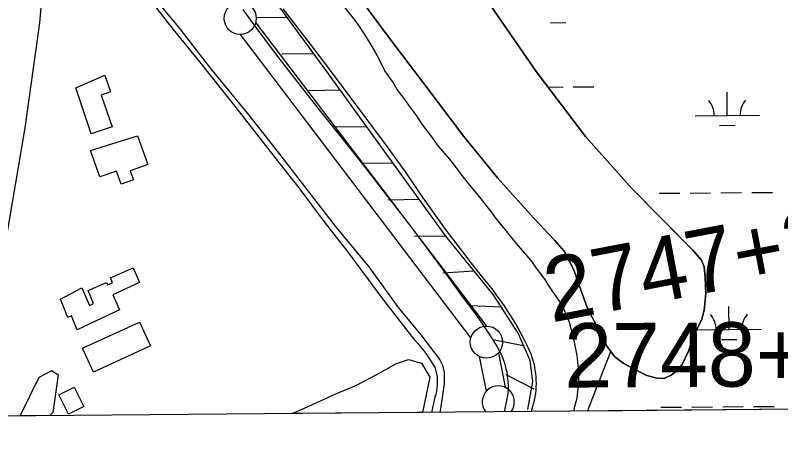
# Model space of a CAD drawing. Extents: x 3568792 to 3606828, y 529143 to 554785.
# Drawn here: x 3574735 to 3575924, y 534531 to 535185 of the extents above; entities that cross this region are included whole.
import ezdxf

# ---------------------------------------------------------------- set-up
doc = ezdxf.new("R2010")
doc.units = 0
for name, color, linetype in [('V-BLDG-OTLN', 7, 'Continuous'), ('V-FLOD-BASE', 7, 'Continuous'), ('V-GRID-FRAM', 7, 'Continuous'), ('V-LEVE-TOET', 7, 'Continuous'), ('V-ROAD-CNTR', 7, 'Continuous'), ('V-RRAP-FSHR', 7, 'Continuous'), ('V-SITE-VEGE', 7, 'Continuous'), ('V-SURV-IDEN', 7, 'Continuous'), ('V-SURV-LINE', 7, 'Continuous'), ('V-TOPO-SHOR', 7, 'Continuous'), ('V-WETL-SWMP', 7, 'Continuous')]:
    doc.layers.add(name, color=color, linetype=linetype)

msp = doc.modelspace()

# ---------------------------------------------------------------- linework, layer by layer
at = {"layer": 'V-BLDG-OTLN'}
for points in [[(3574828.5, 535072.1), (3574873.6, 535091.6), (3574882.4, 535065.6), (3574868.1, 535060.8), (3574884.8, 535011.3), (3574852.6, 535000.5)], [(3574924.4, 534997.2), (3574940.4, 534952.7), (3574913.1, 534942.8), (3574918, 534929.2), (3574899, 534922.4), (3574891.7, 534942.7), (3574866.1, 534933.5), (3574851.3, 534974.6)], [(3574804.8, 534743.6), (3574837.7, 534761.3), (3574849.9, 534733.7), (3574856.1, 534736.9), (3574847.6, 534756.8), (3574876.3, 534769.5), (3574878, 534765.6), (3574885.7, 534769), (3574882.5, 534776.8), (3574917.6, 534792.5), (3574927.4, 534769.4), (3574886.2, 534750.5), (3574896.5, 534726.8), (3574830.9, 534695.7), (3574821.9, 534717.4), (3574816.1, 534715.1)], [(3574838.7, 534667.3), (3574927.3, 534707.8), (3574944.4, 534670.9), (3574856, 534630)], [(3574825.8, 534607), (3574841.1, 534576.9), (3574817.3, 534564.8), (3574802.1, 534595)]]:
    msp.add_lwpolyline(points, close=True, dxfattribs=at)
at = {"layer": 'V-FLOD-BASE'}
msp.add_lwpolyline([(3575088.3, 535193.6), (3575102.7, 535173.5), (3575122.3, 535147.1), (3575142.1, 535120.8), (3575162.2, 535094.8), (3575182.4, 535068.8), (3575202.8, 535043.1), (3575223.4, 535017.4), (3575248.8, 534985.6), (3575274.1, 534953.6), (3575299.1, 534921.5), (3575324, 534889.2), (3575348.7, 534856.8), (3575373.1, 534824.2), (3575390.6, 534800.7), (3575407.9, 534777), (3575425.1, 534753.2), (3575433.9, 534741.6), (3575442.6, 534729.9), (3575451.2, 534718), (3575459.5, 534706), (3575467.7, 534693.9), (3575475.7, 534681.7), (3575483.4, 534669.4), (3575486, 534664.8), (3575488.4, 534660.1), (3575490.5, 534655.4), (3575492.5, 534650.5), (3575494.2, 534645.6), (3575495.8, 534640.6), (3575497.1, 534635.5), (3575498.2, 534630.4), (3575499.1, 534625.2), (3575499.7, 534620), (3575500.1, 534614.8), (3575500.3, 534609.6), (3575500.3, 534604.3), (3575500, 534599.1), (3575499.6, 534593.9), (3575494.3, 534568.5)], dxfattribs=at)
at = {"layer": 'V-GRID-FRAM'}
msp.add_lwpolyline([(3570936, 552713.8), (3602582.8, 552980.8), (3602744.1, 534798.4), (3571081.5, 534531.3), (3570936, 552713.8)], dxfattribs=at)
at = {"layer": 'V-LEVE-TOET'}
for points in [[(3574956.4, 535204.1), (3574987.9, 535166.5), (3575038, 535102), (3575097.3, 535029.7), (3575143.5, 534970.8), (3575196.5, 534902.8), (3575231.6, 534856.8), (3575284, 534793.7), (3575329.8, 534730.7), (3575364.6, 534688.1), (3575394.2, 534649.5), (3575398.6, 534641), (3575401, 534629.5), (3575401.3, 534611.9), (3575395.1, 534573.2), (3575394.1, 534567.7)], [(3575150.3, 535194.9), (3575164.6, 535176.4), (3575194.3, 535137.9), (3575223.7, 535099.2), (3575252.9, 535060.4), (3575282, 535021.5), (3575310.8, 534982.3), (3575339.4, 534943.1), (3575351.7, 534924.7), (3575364.3, 534906.5), (3575376.9, 534888.4), (3575389.8, 534870.4), (3575402.8, 534852.6), (3575416, 534834.8), (3575429.3, 534817.2), (3575442.8, 534799.7), (3575456.5, 534782.4), (3575470.3, 534765.1), (3575476.5, 534757.3), (3575482.6, 534749.3), (3575488.5, 534741.2), (3575494.2, 534733), (3575499.7, 534724.6), (3575505.1, 534716.2), (3575510.3, 534707.6), (3575515.3, 534698.9), (3575520.2, 534690.2), (3575524.8, 534681.3), (3575529.3, 534672.3), (3575533.6, 534663.3), (3575535.5, 534658.4), (3575537.3, 534653.5), (3575538.8, 534648.6), (3575540.2, 534643.5), (3575541.3, 534638.4), (3575542.2, 534633.3)], [(3575542.2, 534633.3), (3575542.9, 534628.2), (3575543.4, 534623), (3575543.7, 534617.8), (3575543.8, 534612.6), (3575543.7, 534607.4), (3575543.3, 534602.2), (3575542.8, 534597), (3575542, 534591.8), (3575541, 534586.7), (3575539.8, 534581.7), (3575538.5, 534576.6), (3575536.5, 534568.9)]]:
    msp.add_lwpolyline(points, dxfattribs=at)
at = {"layer": 'V-ROAD-CNTR'}
msp.add_lwpolyline([(3574679.5, 534564.9), (3574682.8, 534585.3), (3574715.6, 534808.4), (3574750, 535010.1), (3574772.8, 535172.9), (3574780.1, 535257.5), (3574780.7, 535303.2), (3574778.8, 535343.1), (3574770, 535401.7), (3574752.2, 535470.8), (3574725.1, 535558.5), (3574678.7, 535714.1), (3574618.7, 535912.6), (3574554, 536132.9), (3574534.5, 536220.7), (3574522.9, 536264.9), (3574502.7, 536365.9), (3574469.6, 536535.8)], dxfattribs=at)
at = {"layer": 'V-RRAP-FSHR'}
for p, q in [((3575157, 535181.6), (3575108.2, 535180.8)), ((3575198.2, 535125), (3575149.4, 535124.2)), ((3575239.3, 535068.4), (3575190.5, 535067.6)), ((3575280.4, 535011.7), (3575231.6, 535010.9)), ((3575321.5, 534955), (3575272.7, 534954.2)), ((3575362.6, 534898.3), (3575313.7, 534897.6)), ((3575403.6, 534841.7), (3575354.8, 534840.9)), ((3575447.6, 534787.2), (3575398.8, 534783.8)), ((3575489.6, 534731.3), (3575440.8, 534733.1)), ((3575524.6, 534670.9), (3575476.7, 534680.4)), ((3575540.7, 534603.4), (3575497.3, 534625.7))]:
    msp.add_line(p, q, dxfattribs=at)
msp.add_lwpolyline([(3575531.2, 534572.1), (3575539, 534615.7), (3575534.6, 534648.2), (3575515.9, 534690.6), (3575477.1, 534750.6), (3575403.9, 534841.3), (3575218.5, 535097.2), (3575070.7, 535300.3), (3575019.9, 535377.2), (3574957.7, 535513.9), (3574913.3, 535625.4), (3574863.8, 535751.1), (3574795.8, 535973.3), (3574724.4, 536223.4), (3574678.3, 536411.2)], dxfattribs=at)
at = {"layer": 'V-SITE-VEGE'}
for p, q in [((3575251.7, 535236.1), (3575312.4, 535154)), ((3575265.1, 535173.6), (3575234.2, 535213.7)), ((3575543.9, 535097.7), (3575473.8, 535199.4)), ((3575275.9, 535158.2), (3575265.1, 535173.6)), ((3575287.3, 535140), (3575275.9, 535158.2)), ((3575312.4, 535154), (3575371.1, 535076.7)), ((3575293, 535130), (3575287.3, 535140)), ((3575302.6, 535111.2), (3575293, 535130)), ((3575308.8, 535098.3), (3575302.6, 535111.2)), ((3575321.4, 535081.2), (3575308.8, 535098.3)), ((3575620.9, 534996.5), (3575543.9, 535097.7)), ((3575328.2, 535069.4), (3575321.4, 535081.2)), ((3575339.1, 535055.3), (3575328.2, 535069.4)), ((3575371.1, 535076.7), (3575431.7, 534996.4)), ((3575345.9, 535045.3), (3575339.1, 535055.3)), ((3575358.5, 535028.8), (3575345.9, 535045.3)), ((3575367.1, 535015.8), (3575358.5, 535028.8)), ((3575381.9, 534995.8), (3575367.1, 535015.8)), ((3575392.2, 534981.6), (3575381.9, 534995.8)), ((3575431.7, 534996.4), (3575484.2, 534932.1)), ((3575693.5, 534915.2), (3575620.9, 534996.5)), ((3575409.4, 534961.5), (3575392.2, 534981.6)), ((3575415.1, 534954.5), (3575409.4, 534961.5)), ((3575431.1, 534933.2), (3575415.1, 534954.5)), ((3575441.4, 534920.3), (3575431.1, 534933.2)), ((3575484.2, 534932.1), (3575539.7, 534870.1)), ((3575456.3, 534902), (3575441.4, 534920.3)), ((3575787.5, 534819.5), (3575693.5, 534915.2)), ((3575475.8, 534877.8), (3575456.3, 534902)), ((3575482.1, 534868.9), (3575475.8, 534877.8)), ((3575500.4, 534845.9), (3575482.1, 534868.9)), ((3575539.7, 534870.1), (3575572.4, 534835.2)), ((3575513.6, 534830), (3575500.4, 534845.9)), ((3575572.4, 534835.2), (3575587.3, 534818.2)), ((3575532.5, 534807.6), (3575513.6, 534830)), ((3575587.3, 534818.2), (3575595.9, 534802.5)), ((3575800.8, 534804.1), (3575787.5, 534819.5)), ((3575538.2, 534801.1), (3575532.5, 534807.6)), ((3575542.8, 534794), (3575538.2, 534801.1)), ((3575595.9, 534802.5), (3575603.1, 534787.8)), ((3575805.1, 534793.8), (3575800.8, 534804.1)), ((3575547.9, 534787.5), (3575542.8, 534794)), ((3575558.2, 534773.9), (3575547.9, 534787.5)), ((3575603.1, 534787.8), (3575608.8, 534771.1)), ((3575806.9, 534777.8), (3575805.1, 534793.8)), ((3575564.5, 534763.9), (3575558.2, 534773.9)), ((3575807.8, 534752.3), (3575806.9, 534777.8)), ((3575570.2, 534755.7), (3575564.5, 534763.9)), ((3575608.8, 534771.1), (3575615.8, 534750.9)), ((3575578.2, 534743.3), (3575570.2, 534755.7)), ((3575615.8, 534750.9), (3575623.3, 534730.7)), ((3575805.1, 534726.3), (3575807.8, 534752.3)), ((3575583.3, 534735.7), (3575578.2, 534743.3)), ((3575588.9, 534723.9), (3575583.3, 534735.7)), ((3575623.3, 534730.7), (3575654.6, 534670.1)), ((3575801.5, 534712.7), (3575805.1, 534726.3)), ((3575591.8, 534718.6), (3575588.9, 534723.9)), ((3575595.7, 534707.5), (3575591.8, 534718.6)), ((3575793.2, 534695.6), (3575801.5, 534712.7)), ((3575598.5, 534697.6), (3575595.7, 534707.5)), ((3575602.9, 534679.4), (3575598.5, 534697.6)), ((3575785.6, 534677.2), (3575793.2, 534695.6)), ((3575607.8, 534656), (3575602.9, 534679.4)), ((3575780.6, 534662.5), (3575785.6, 534677.2)), ((3575654.6, 534670.1), (3575665.7, 534654.6)), ((3575609.8, 534635.6), (3575607.8, 534656)), ((3575665.7, 534654.6), (3575679.5, 534644.1)), ((3575770.7, 534641.8), (3575780.6, 534662.5)), ((3575295.4, 534625.7), (3575327.1, 534643.7)), ((3575327.1, 534643.7), (3575345.7, 534649.6)), ((3575345.7, 534649.6), (3575366, 534644.3)), ((3575366, 534644.3), (3575378.7, 534622.5)), ((3575679.5, 534644.1), (3575693.9, 534636.3)), ((3575763.6, 534632.6), (3575770.7, 534641.8)), ((3574771.6, 534622.5), (3574791.5, 534632.7)), ((3574791.5, 534632.7), (3574801.2, 534625.8)), ((3575610.2, 534623.9), (3575609.8, 534635.6)), ((3575693.9, 534636.3), (3575715.9, 534625.1)), ((3575753.6, 534625.2), (3575763.6, 534632.6)), ((3574742.1, 534562.2), (3574771.6, 534622.5)), ((3574801.2, 534625.8), (3574798.5, 534607.3)), ((3575263.7, 534609.5), (3575295.4, 534625.7)), ((3575378.7, 534622.5), (3575367.3, 534567.5)), ((3575610, 534608.8), (3575610.2, 534623.9)), ((3575715.9, 534625.1), (3575731.4, 534621)), ((3575731.4, 534621), (3575742.9, 534620.4)), ((3575742.9, 534620.4), (3575753.6, 534625.2)), ((3574798.5, 534607.3), (3574792.9, 534567.3)), ((3575232.7, 534596.4), (3575263.7, 534609.5)), ((3575607.9, 534590.1), (3575610, 534608.8)), ((3575184.2, 534574.3), (3575232.7, 534596.4)), ((3575603.6, 534575.1), (3575607.9, 534590.1)), ((3575164.7, 534565.8), (3575184.2, 534574.3)), ((3575603, 534569.5), (3575603.6, 534575.1)), ((3575948.4, 534572.4), (3575603, 534569.5)), ((3574788.1, 534562.6), (3574742.1, 534562.2)), ((3574792.9, 534567.3), (3574788.1, 534562.6)), ((3575367.3, 534567.5), (3575164.7, 534565.8))]:
    msp.add_line(p, q, dxfattribs=at)
at = {"layer": 'V-SURV-LINE'}
for points in [[(3575108.1, 535173.2), (3575466.6, 534701.8)], [(3575442.7, 534683.6), (3575084.3, 535155.1)], [(3575466.6, 534600.6), (3575455.9, 534654.2)], [(3575485.3, 534660.1), (3575496, 534606.5)]]:
    msp.add_lwpolyline(points, dxfattribs=at)
for centre in [(3575084.1, 535180.1), (3575466.7, 534676.8)]:
    msp.add_circle(centre, 25, dxfattribs=at)
msp.add_arc((3575485.2, 534583.9), 25, 322.3071, 218.6596, dxfattribs=at)
at = {"layer": 'V-TOPO-SHOR'}
msp.add_line((3575344.6, 534693.1), (3575354.4, 534680.7), dxfattribs=at)
for points in [[(3574756.1, 535561.1), (3574778.7, 535526.8), (3574796.2, 535490.7), (3574839.6, 535405.8), (3574889, 535309.9), (3574930.7, 535235.7), (3574948, 535203.3), (3574980, 535162.7), (3575020.8, 535112.3), (3575077.1, 535041.6), (3575139.8, 534961.4), (3575175.2, 534916.4), (3575214.4, 534863.6), (3575250.4, 534818.4), (3575303.6, 534746.4), (3575341, 534697.9), (3575344.6, 534693.1)], [(3575473.8, 535199.4), (3575543.9, 535097.7), (3575620.9, 534996.5), (3575693.5, 534915.2), (3575772.9, 534834.3), (3575787.5, 534819.5), (3575800.8, 534804.1), (3575805.1, 534793.8), (3575806.9, 534777.8), (3575807.8, 534752.3), (3575805.1, 534726.3), (3575801.5, 534712.7), (3575793.2, 534695.6), (3575785.6, 534677.2), (3575780.6, 534662.5), (3575770.7, 534641.8), (3575763.6, 534632.6), (3575753.6, 534625.2), (3575742.9, 534620.4), (3575731.4, 534621), (3575715.9, 534625.1), (3575693.9, 534636.3), (3575679.5, 534644.1), (3575665.7, 534654.6), (3575654.6, 534670.1), (3575647.8, 534683.2), (3575623.3, 534730.7), (3575615.8, 534750.9), (3575608.8, 534771.1), (3575603.1, 534787.8), (3575595.9, 534802.5), (3575587.3, 534818.2), (3575572.4, 534835.2), (3575539.7, 534870.1), (3575484.2, 534932.1), (3575431.7, 534996.4), (3575371.1, 535076.7), (3575312.4, 535154), (3575251.7, 535236.1)], [(3575354.4, 534680.7), (3575359.6, 534675), (3575364.6, 534669.1), (3575369.4, 534663.1), (3575374, 534656.9), (3575378.4, 534650.6), (3575382.6, 534644.2), (3575386.6, 534637.6), (3575387.7, 534633.7), (3575388.7, 534629.7), (3575389.4, 534625.6), (3575390, 534621.5), (3575390.3, 534617.4), (3575390.3, 534613.3), (3575390.2, 534609.2), (3575389.8, 534605.1), (3575389.2, 534601), (3575388.4, 534597), (3575387.3, 534593), (3575386, 534589.1), (3575381.5, 534567.6)]]:
    msp.add_lwpolyline(points, dxfattribs=at)
at = {"layer": 'V-WETL-SWMP'}
for p, q in [((3575543.9, 535097.7), (3575473.8, 535199.4)), ((3575566.3, 535173.2), (3575590.3, 535173.4)), ((3575620.9, 534996.5), (3575543.9, 535097.7)), ((3575562.5, 535073.2), (3575585.8, 535073.4)), ((3575601.8, 535073.5), (3575633.8, 535073.8)), ((3575841, 535029.1), (3575840.7, 535065.1)), ((3575791, 535028.7), (3575891, 535029.5)), ((3575829.1, 535013.5), (3575853.1, 535013.8)), ((3575693.5, 534915.2), (3575620.9, 534996.5)), ((3575787.5, 534819.5), (3575693.5, 534915.2)), ((3575735.2, 534908.1), (3575767.2, 534908.4)), ((3575783.2, 534908.5), (3575815.2, 534908.8)), ((3575831.2, 534908.9), (3575863.2, 534909.2)), ((3575879.2, 534909.3), (3575911.2, 534909.6)), ((3575800.8, 534804.1), (3575787.5, 534819.5)), ((3575805.1, 534793.8), (3575800.8, 534804.1)), ((3575806.9, 534777.8), (3575805.1, 534793.8)), ((3575807.8, 534752.3), (3575806.9, 534777.8)), ((3575805.1, 534726.3), (3575807.8, 534752.3)), ((3575801.4, 534712.7), (3575805.1, 534726.3)), ((3575843.8, 534696.4), (3575843.5, 534732.4)), ((3575793.2, 534695.6), (3575801.4, 534712.7)), ((3575785.5, 534677.2), (3575793.2, 534695.6)), ((3575793.8, 534696), (3575893.8, 534696.8)), ((3575780.6, 534662.5), (3575785.5, 534677.2)), ((3575831.9, 534680.9), (3575855.9, 534681.1)), ((3575623.9, 534569.6), (3575660.1, 534662.4)), ((3575660.1, 534662.4), (3575665.7, 534654.6)), ((3575665.7, 534654.6), (3575679.5, 534644.1)), ((3575770.7, 534641.8), (3575780.6, 534662.5)), ((3575679.5, 534644.1), (3575693.9, 534636.3)), ((3575763.6, 534632.6), (3575770.7, 534641.8)), ((3575693.9, 534636.3), (3575715.9, 534625.1)), ((3575753.6, 534625.2), (3575763.6, 534632.6)), ((3575715.9, 534625.1), (3575731.4, 534621)), ((3575731.4, 534621), (3575742.9, 534620.4)), ((3575742.9, 534620.4), (3575753.6, 534625.2)), ((3575948.3, 534572.4), (3575623.9, 534569.6)), ((3575738, 534575.5), (3575770, 534575.7)), ((3575786, 534575.9), (3575818, 534576.1)), ((3575834, 534576.3), (3575866, 534576.5)), ((3575882, 534576.7), (3575914, 534576.9))]:
    msp.add_line(p, q, dxfattribs=at)
for centre, start, end in [((3575785.7, 535029.1), 359.7115, 41.2552), ((3575896.2, 535030), 139.7115, 181.2552), ((3575788.5, 534696.4), 359.7115, 41.2552), ((3575899, 534697.4), 139.7115, 181.2552)]:
    msp.add_arc(centre, 35.2, start, end, dxfattribs=at)

# ---------------------------------------------------------------- texts
at = {"layer": 'V-SURV-IDEN'}
for s, rotation, p in [('2747+20.1', 10.7944, (3575567.6, 534707)), ('2748+14.8', 0.3538, (3575588, 534606))]:
    msp.add_text(s, height=100, rotation=rotation, dxfattribs=at).set_placement(p)

doc.saveas('drawing.dxf')
